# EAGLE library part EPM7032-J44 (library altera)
EPM7032 MAX 7000 family
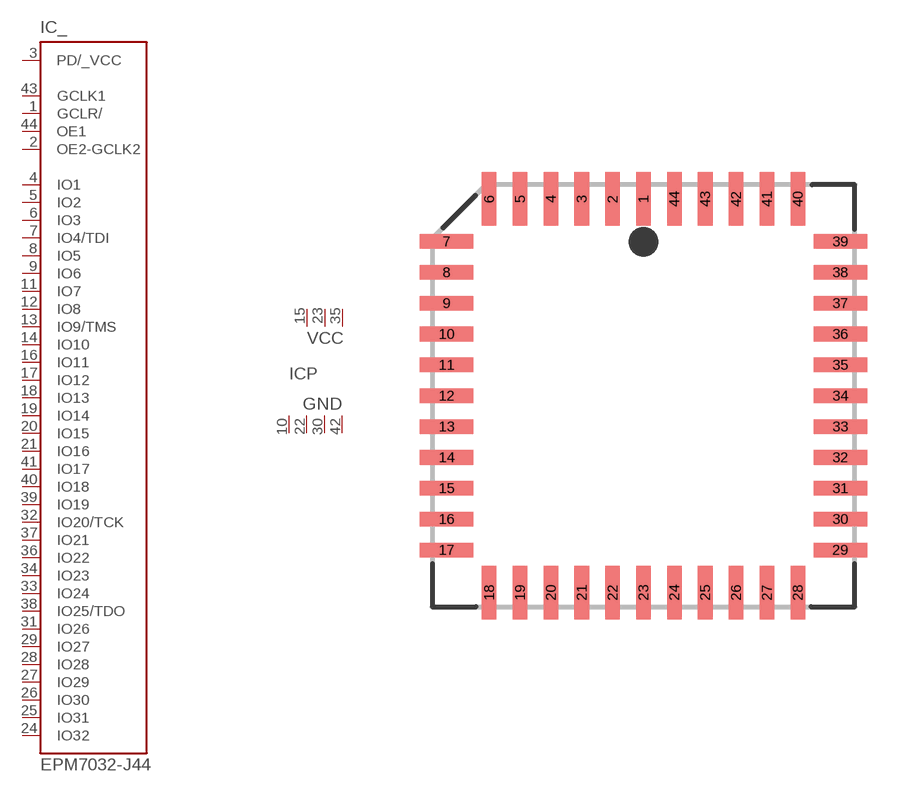
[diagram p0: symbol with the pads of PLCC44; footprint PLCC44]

Designator prefix IC; gates _=EPM7032 P=PWR3-4

## EPM7032-J44  [PLCC44]
1  _:GCLR/  in
2  _:OE2-GCLK2  in
3  _:PD/_VCC  pas
4  _:IO1
5  _:IO2
6  _:IO3
7  _:IO4/TDI
8  _:IO5
9  _:IO6
10  P:GND  pwr
11  _:IO7
12  _:IO8
13  _:IO9/TMS
14  _:IO10
15  P:VCC  pwr
16  _:IO11
17  _:IO12
18  _:IO13
19  _:IO14
20  _:IO15
21  _:IO16
22  P:GND  pwr
23  P:VCC  pwr
24  _:IO32
25  _:IO31
26  _:IO30
27  _:IO29
28  _:IO28
29  _:IO27
30  P:GND  pwr
31  _:IO26
32  _:IO20/TCK
33  _:IO24
34  _:IO23
35  P:VCC  pwr
36  _:IO22
37  _:IO21
38  _:IO25/TDO
39  _:IO19
40  _:IO18
41  _:IO17
42  P:GND  pwr
43  _:GCLK1  in
44  _:OE1  in

## Footprint PLCC44 (pad centres in mm)
Plastic J-Lead Chip Carrier
smd 0.6 x 2.2: 1 0,8.1; 2 -1.27,8.1; 3 -2.54,8.1; 4 -3.81,8.1; 5 -5.08,8.1; 6 -6.35,8.1; 18 -6.35,-8.1; 19 -5.08,-8.1; 20 -3.81,-8.1; 21 -2.54,-8.1; 22 -1.27,-8.1; 23 0,-8.1; 24 1.27,-8.1; 25 2.54,-8.1; 26 3.81,-8.1; 27 5.08,-8.1; 28 6.35,-8.1; 40 6.35,8.1; 41 5.08,8.1; 42 3.81,8.1; 43 2.54,8.1; 44 1.27,8.1
smd 2.2 x 0.6: 7 -8.1,6.35; 8 -8.1,5.08; 9 -8.1,3.81; 10 -8.1,2.54; 11 -8.1,1.27; 12 -8.1,0; 13 -8.1,-1.27; 14 -8.1,-2.54; 15 -8.1,-3.81; 16 -8.1,-5.08; 17 -8.1,-6.35; 29 8.1,-6.35; 30 8.1,-5.08; 31 8.1,-3.81; 32 8.1,-2.54; 33 8.1,-1.27; 34 8.1,0; 35 8.1,1.27; 36 8.1,2.54; 37 8.1,3.81; 38 8.1,5.08; 39 8.1,6.35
